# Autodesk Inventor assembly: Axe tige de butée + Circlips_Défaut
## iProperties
Shininess: 64.0
Length Units: 11269
Angle Units: 11279
Time Units: 11290
Mass Units: 11283
Length Display Precision: 3
Angle Display Precision: 2
Compacted: True
Created: 2006-11
Part Number: Axe tige de butée + Circlips_Défaut
Document SubType Name: Assembly
Designer: profs_sti
Density: 0.0
Volumn: 0.0
Area: 0.0
PropertySet Name: Model Information
Control State: 0
Master: False
Checked Out: False
Author: profs_sti
